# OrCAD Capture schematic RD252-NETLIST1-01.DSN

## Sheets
1 2: size A3
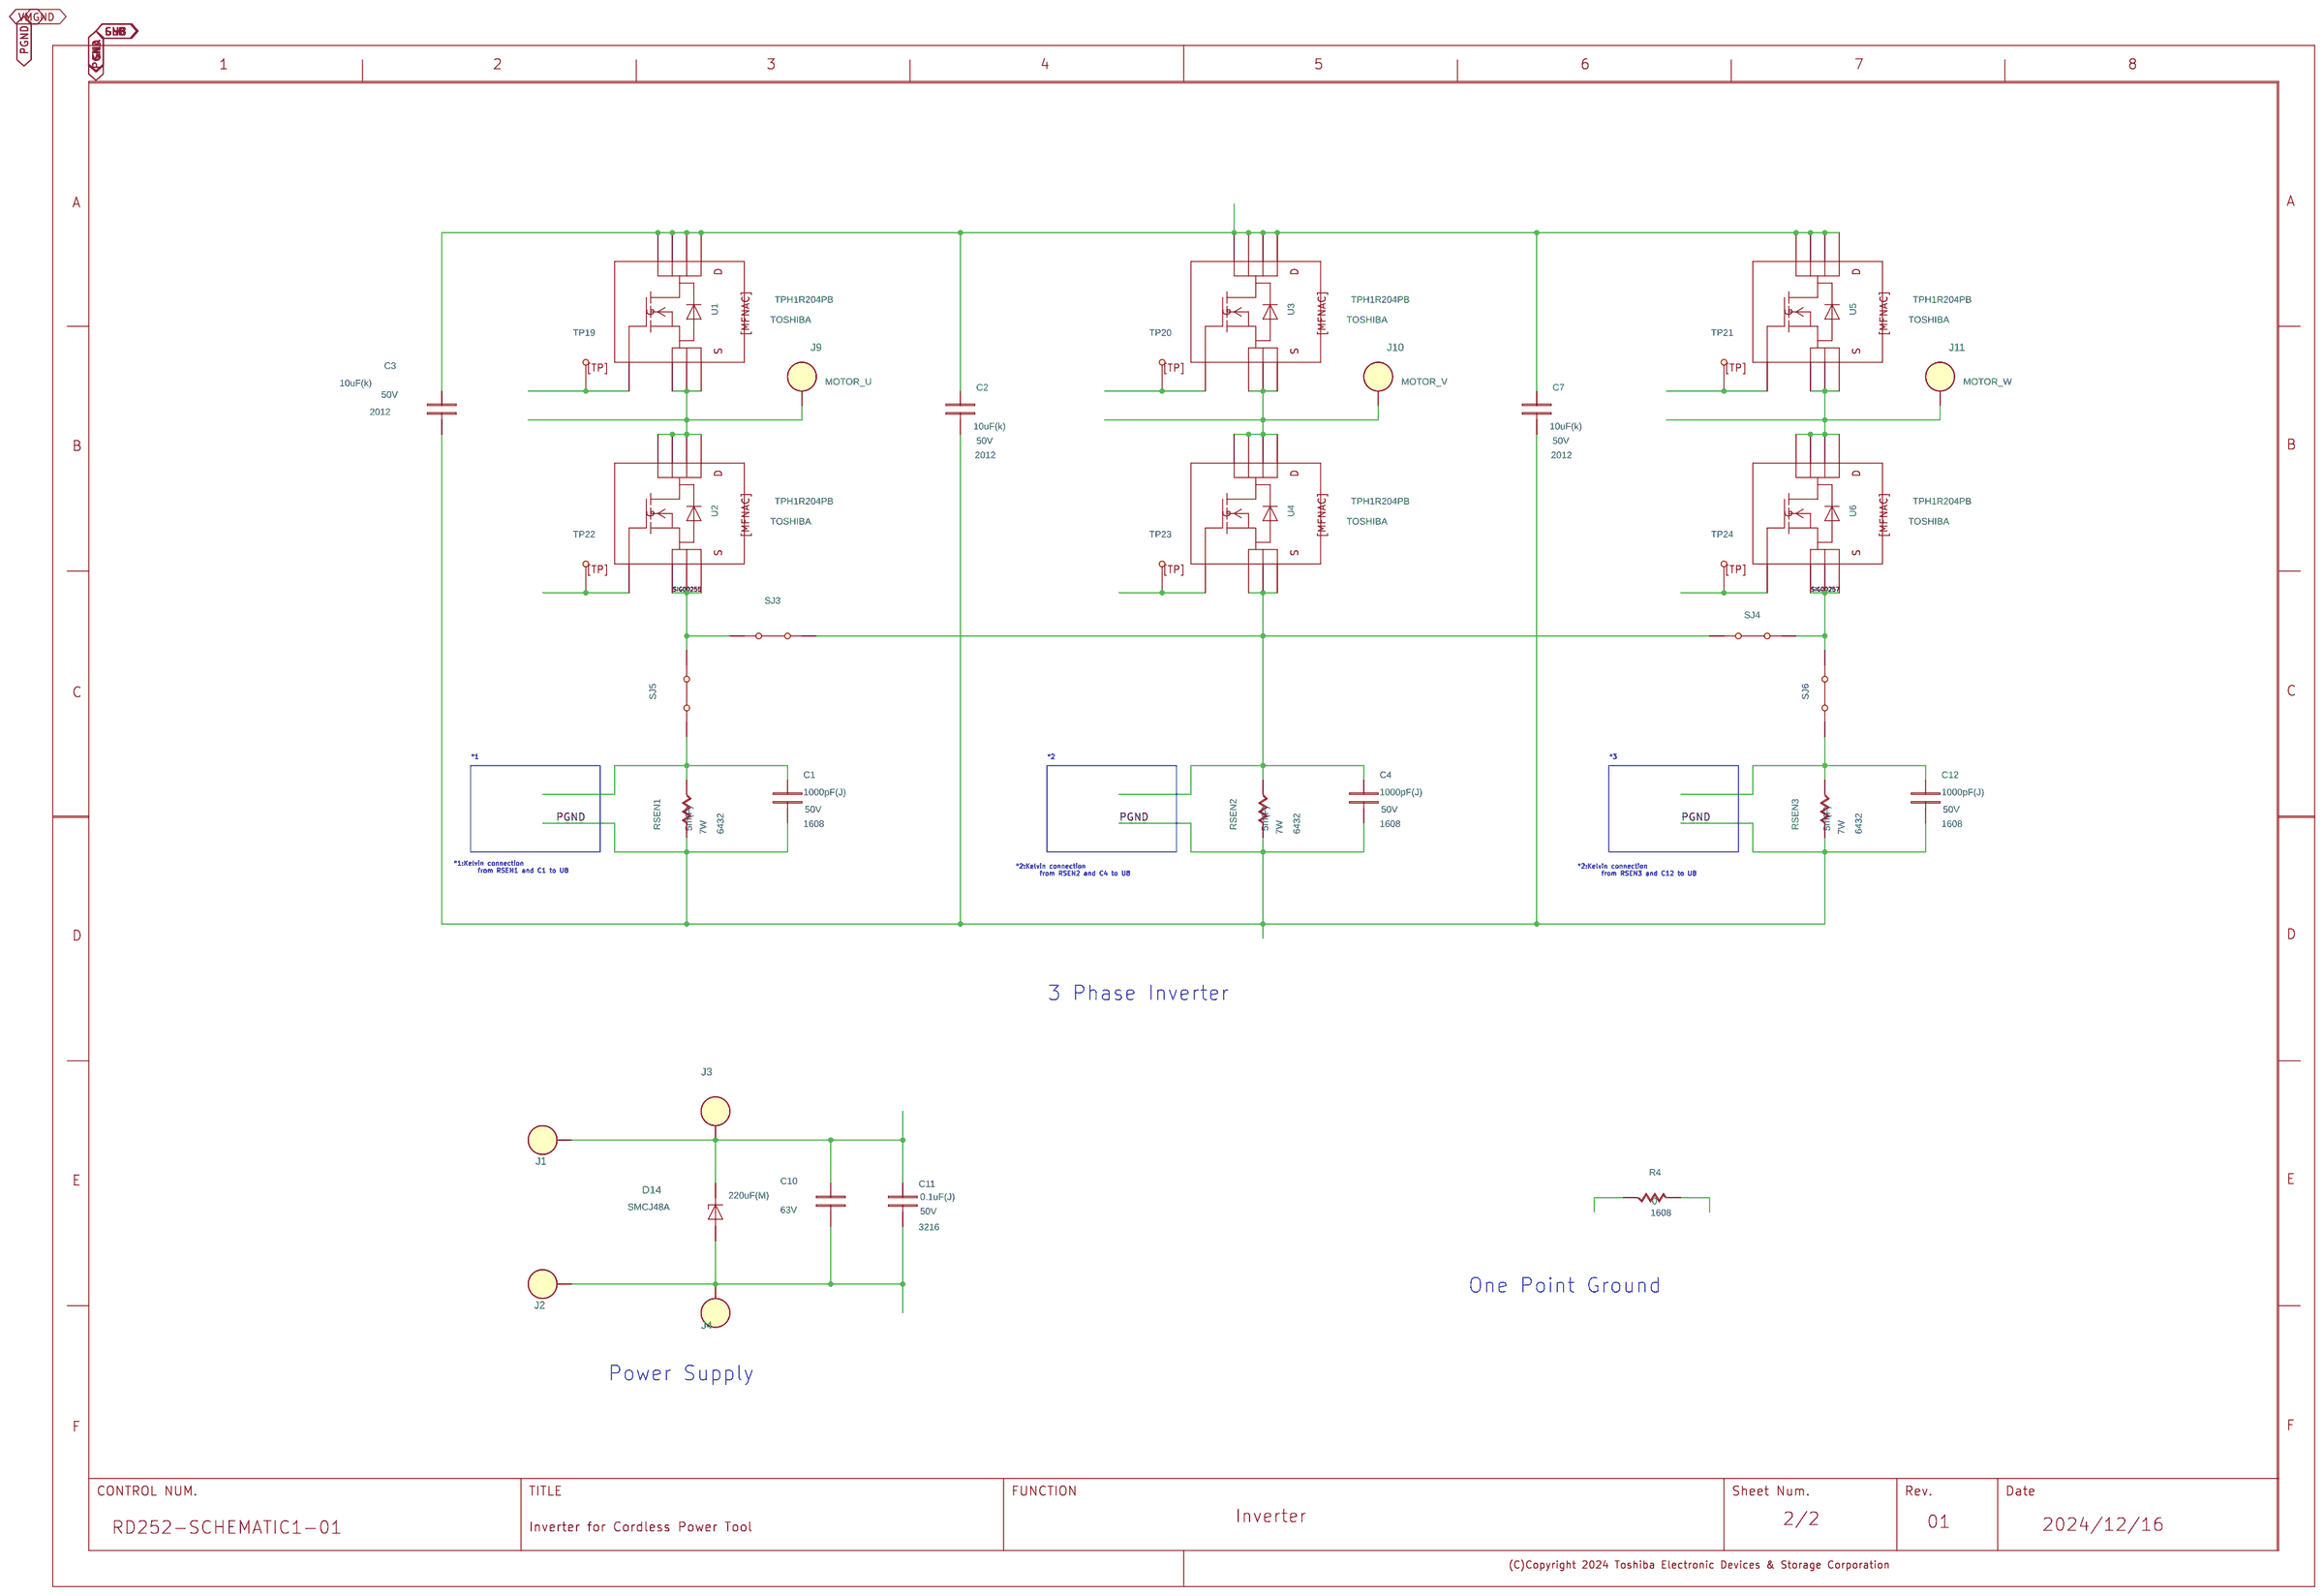
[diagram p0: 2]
2 1: size A3
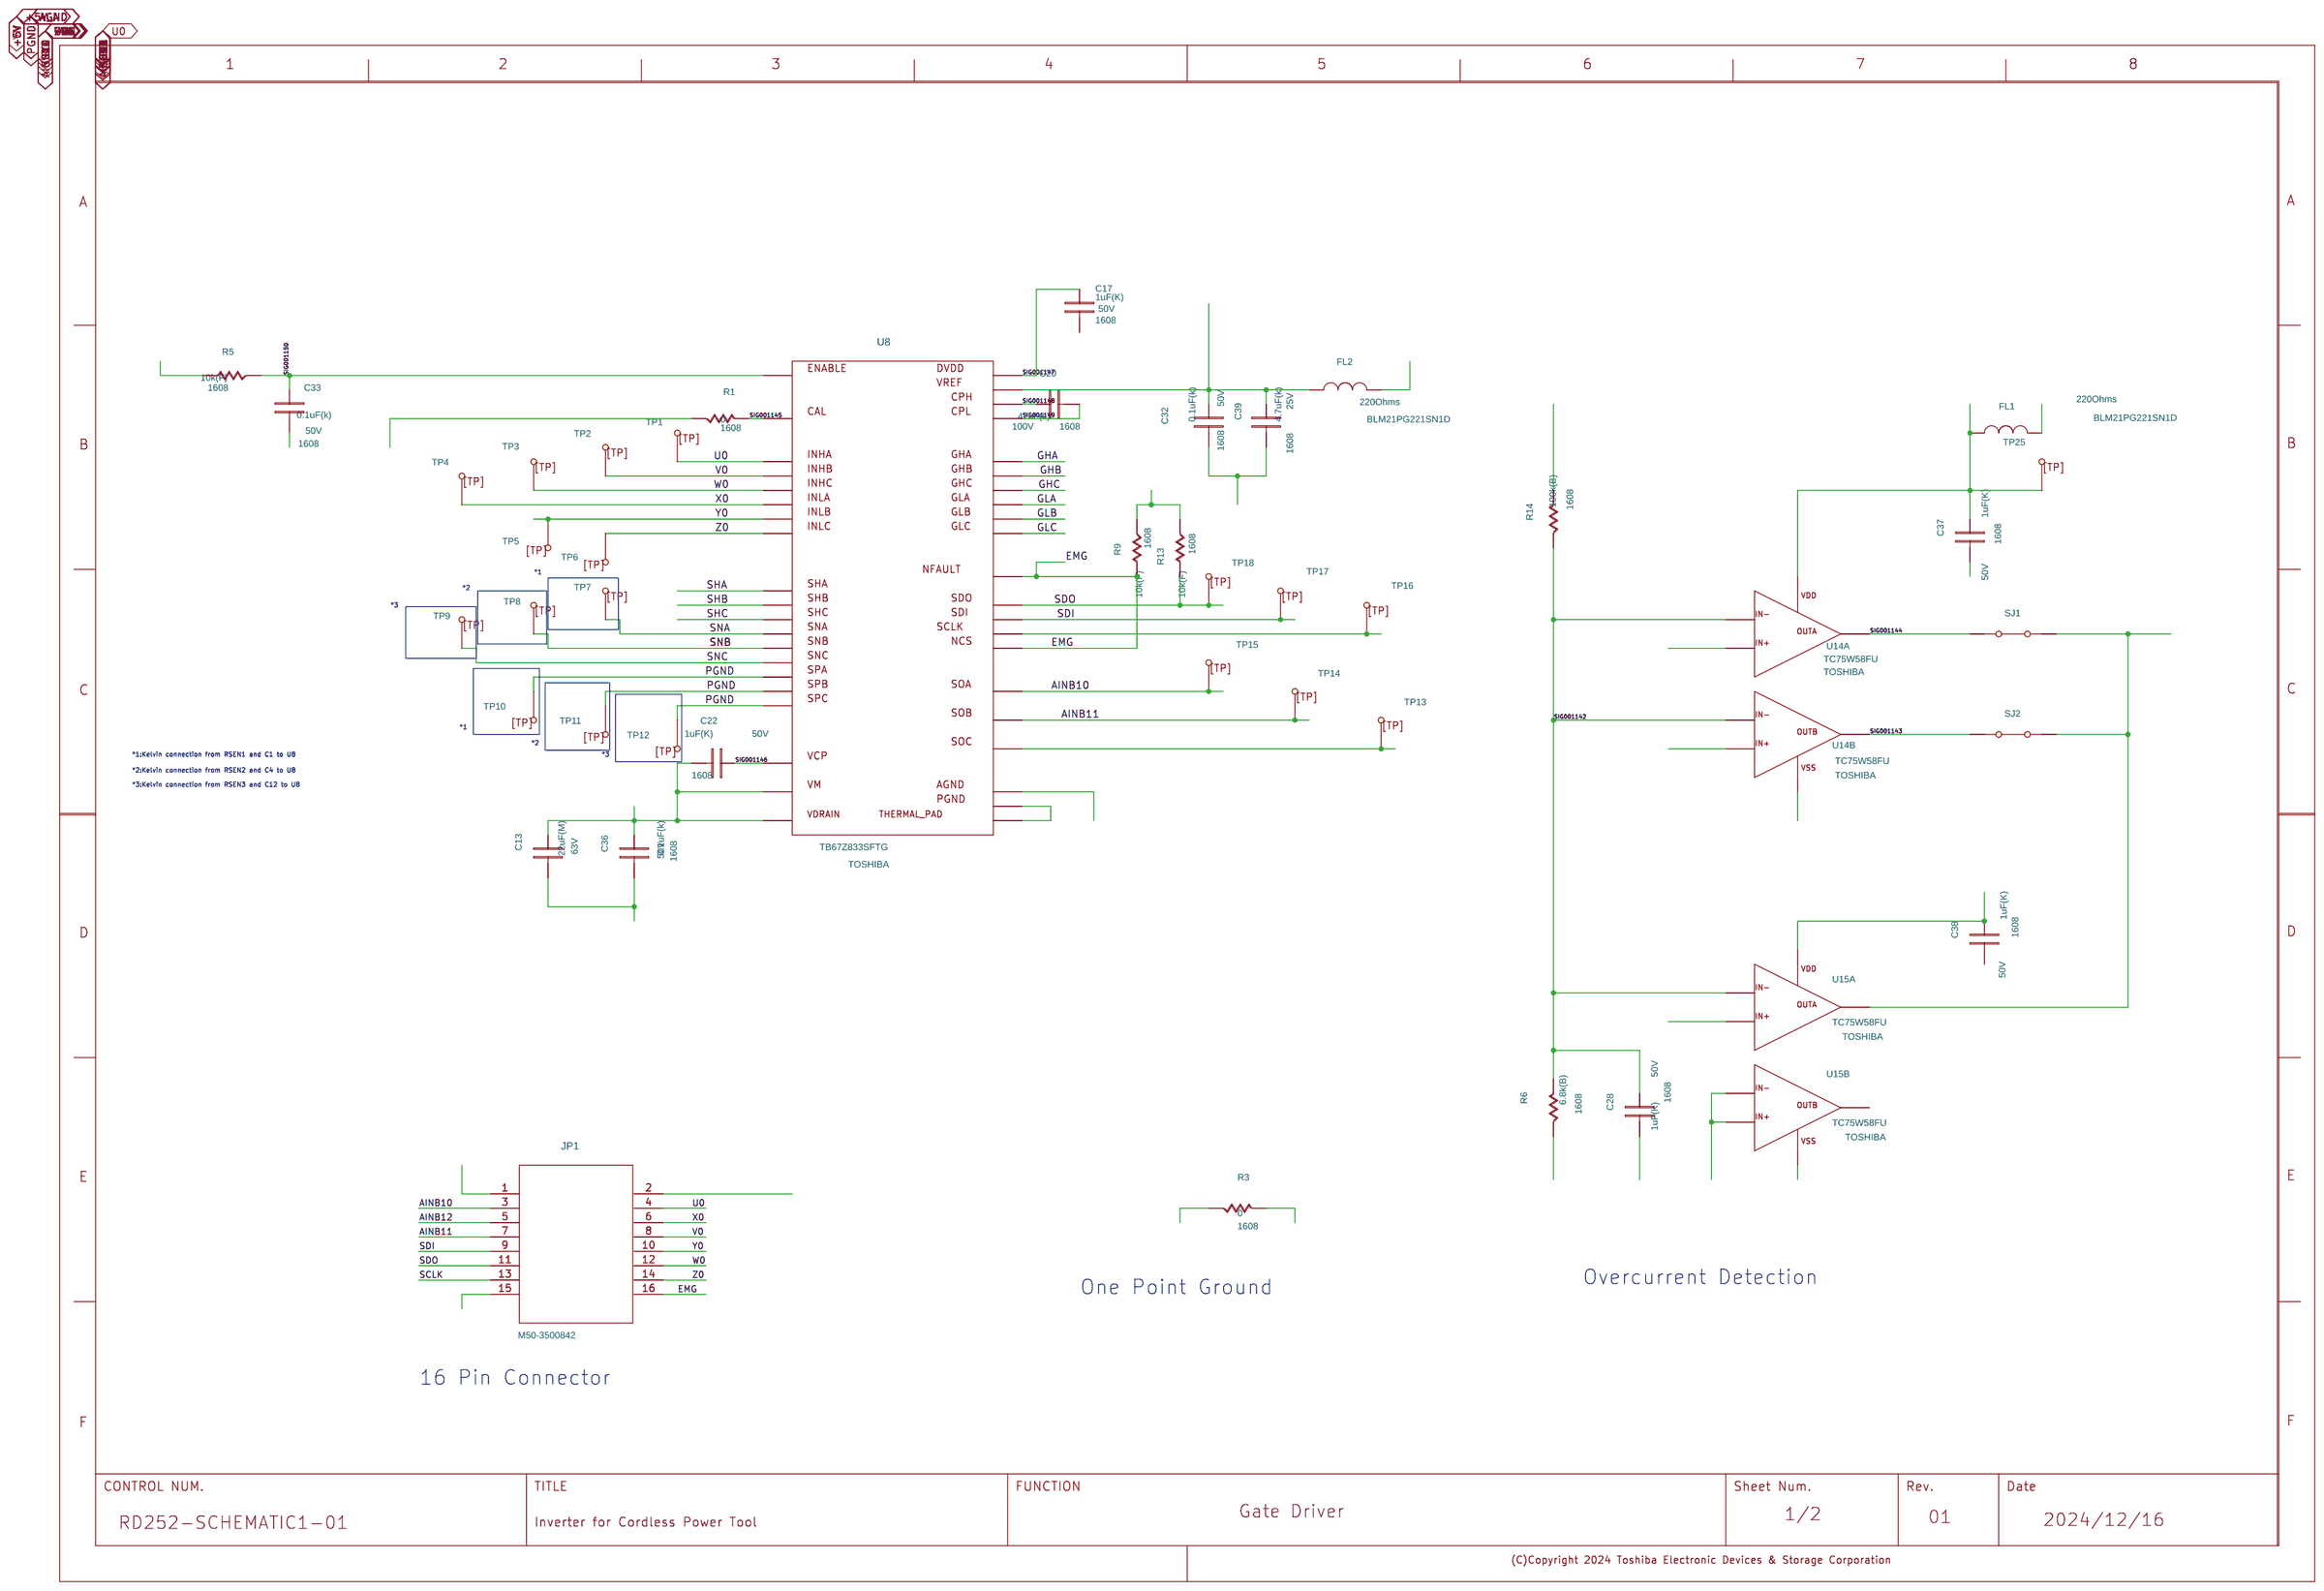
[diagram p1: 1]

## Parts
sheet 1
C13  C
C17  C
C20  C
C22  C
C28  C
C32  C
C33  C
C36  C
C37  C
C38  C
C39  C
FL1  L
FL2  L
JP1  CONN_16PINJ  [IDC16_1_27MM]
R1  R
R3  R
R5  R
R6  R
R9  R
R13  R
R14  R
SJ1  JP
SJ2  JP
TP1  TP
TP2  TP
TP3  TP
TP4  TP
TP5  TP
TP6  TP
TP7  TP
TP8  TP
TP9  TP
TP10  TP
TP11  TP
TP12  TP
TP13  TP
TP14  TP
TP15  TP
TP16  TP
TP17  TP
TP18  TP
TP25  TP
U8  DRV8323S
U14  NA  (sections A,B)
U15  NA  (sections A,B)
U?#1  WAKU_DEF100
sheet 2
C1  C
C2  C
C3  C
C4  C
C7  C
C10  C
C11  C
C12  C
D14  SMCJ22A  [DSMC]
J1  INV  [TP_SM]
J2  PGND  [TP_SM]
J3  INV  [TP_SM]
J4  PGND  [TP_SM]
J9  MOTOR_U  [TP_SM]
J10  MOTOR_U  [TP_SM]
J11  MOTOR_U  [TP_SM]
R4  R
RSEN1  R
RSEN2  R
RSEN3  R
SJ3  JP
SJ4  JP
SJ5  JP
SJ6  JP
TP19  TP
TP20  TP
TP21  TP
TP22  TP
TP23  TP
TP24  TP
U1  MFNAC
U2  MFNAC
U3  MFNAC
U4  MFNAC
U5  MFNAC
U6  MFNAC
U?#2  WAKU_DEF100

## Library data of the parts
C13 = C: COMPONENTKIND: 0; COMPONENTTYPE: 4; VAL1: 22uF(M); VAL2: 63V
C17 C37 C38 = C: COMPONENTTYPE: 4; SIZECODESMD: 1608; VAL1: 1uF(K); VAL2: 50V
C20 = C: COMPONENTKIND: 0; COMPONENTTYPE: 4; SIZECODESMD: 1608; VAL1: 47nF(k); VAL2: 100V
C22 C28 = C: COMPONENTKIND: 0; COMPONENTTYPE: 4; SIZECODESMD: 1608; VAL1: 1uF(K); VAL2: 50V
C32 C33 = C: COMPONENTTYPE: 4; SIZECODESMD: 1608; VAL1: 0.1uF(k); VAL2: 50V
C36 = C: COMPONENTKIND: 0; COMPONENTTYPE: 4; SIZECODESMD: 1608; VAL1: 0.1uF(k); VAL2: 50V
C39 = C: COMPONENTTYPE: 4; SIZECODESMD: 1608; VAL1: 4.7uF(k); VAL2: 25V
FL1 FL2 = L: COMPONENTTYPE: 4; VAL1: 220Ohms; VAL3: BLM21PG221SN1D
JP1 = CONN_16PINJ_JP1: COMPONENTKIND: 114; COMPONENTTYPE: 4; INSTANCENAME: INS1151; VAL3: M50-3500842
R1 = R: COMPONENTKIND: 0; COMPONENTTYPE: 4; SIZECODESMD: 1608; VAL1: 0; VAL2: 1A
R3 R4 = R: COMPONENTTYPE: 4; SIZECODESMD: 1608; VAL1: 0; VAL2: 1A
R5 R9 R13 = R: COMPONENTKIND: 0; COMPONENTTYPE: 4; SIZECODESMD: 1608; VAL1: 10k(F); VAL2: 330mW
R6 = R: COMPONENTTYPE: 4; SIZECODESMD: 1608; VAL1: 6.8k(B); VAL2: 200mW
R14 = R: COMPONENTTYPE: 4; SIZECODESMD: 1608; VAL1: 100k(B); VAL2: 200mW
SJ1-SJ6 = JP: COMP: SJ; COMPONENTTYPE: 4; SAVECOUNT: 0; VAL3: Solder_Jumper
TP1-TP25 = TP: COMPONENTTYPE: 4
U8 = TB67Z833SFTG_U8: COMPONENTTYPE: 4; SAVECOUNT: 3; UPDATEDATE: 2025/1/16; UPDATETIME: 19:51:29; USERCOMPTEXT3: TOSHIBA; VAL3: TB67Z833SFTG
U14 = TC75W58FU_1: COMP: TC75W58FU; COMPONENTTYPE: 8; CaptureCellPackProp: TC75W58FU_1A; SAVECOUNT: 7; UPDATEDATE: 2024/11/5; UPDATETIME: 17:40:12; USERCOMPTEXT3: TOSHIBA; VAL3: TC75W58FU
U15 = TC75W58FU_1: COMP: TC75W58FU; COMPONENTTYPE: 8; CaptureCellPackProp: TC75W58FU_1A; USERCOMPTEXT3: TOSHIBA; VAL3: TC75W58FU
U?#1 = WAKU_DEF100_1: COMPONENTTYPE: 2; DATE: 2024/12/16; DRAWINGNUMBER: RD252-SCHEMATIC1-01; FUNCTION: Gate Driver; REVISION: 01; SHEETNUMBER: 1/2; SHTSAVECOUNT: 91; TITLE: Inverter for Cordless Power Tool; UPDATEDATE: 2025.1.27; UPDATETIME: 15:35:51
C1 C4 C12 = C: COMPONENTKIND: 0; COMPONENTTYPE: 4; SIZECODESMD: 1608; VAL1: 1000pF(J); VAL2: 50V
C2 C3 C7 = C: COMPONENTTYPE: 4; SIZECODESMD: 2012; VAL1: 10uF(k); VAL2: 50V
C10 = C: COMPONENTTYPE: 4; VAL1: 220uF(M); VAL2: 63V
C11 = C: COMPONENTTYPE: 4; SIZECODESMD: 3216; VAL1: 0.1uF(J); VAL2: 50V
D14 = SMCJ22A_D14: COMP: SMCJ48A; COMPONENTKIND: 103; COMPONENTTYPE: 4; INSTANCENAME: INS1233; VAL3: SMCJ48A
J1 = 1X1HEADER_J1: COMPONENTTYPE: 4; INSTANCENAME: INS1187; SAVECOUNT: 3; UPDATEDATE: 2024/10/21; UPDATETIME: 10:49:18; UPDATEUSER: sptcae09; VAL3: Through Hole
J2 = 1X1HEADER_J2: COMPONENTTYPE: 4; INSTANCENAME: INS1195; SAVECOUNT: 3; UPDATEDATE: 2024/10/21; UPDATETIME: 10:49:19; UPDATEUSER: sptcae09; VAL3: Through Hole
J3 = 1X1HEADER_J3: COMPONENTTYPE: 4; INSTANCENAME: INS1429; SAVECOUNT: 3; UPDATEDATE: 2024/10/21; UPDATETIME: 10:49:12; UPDATEUSER: sptcae09; VAL3: Through Hole
J4 = 1X1HEADER_J4: COMPONENTTYPE: 4; INSTANCENAME: INS1437; SAVECOUNT: 3; UPDATEDATE: 2024/10/21; UPDATETIME: 10:49:13; UPDATEUSER: sptcae09; VAL3: Through Hole
J9 = 1X1HEADER_J9: COMPONENTTYPE: 4; INSTANCENAME: INS1015; SAVECOUNT: 3; UPDATEDATE: 2024/10/21; UPDATETIME: 10:49:12; UPDATEUSER: sptcae09; USEWITHLAYOUT: YES
J10 = 1X1HEADER_J9: COMPONENTTYPE: 4; INSTANCENAME: INS1015; SAVECOUNT: 3; UPDATEDATE: 2024/10/21; UPDATETIME: 10:49:12; UPDATEUSER: sptcae09; USEWITHLAYOUT: YES; VAL3: MOTOR_V
J11 = 1X1HEADER_J9: COMPONENTTYPE: 4; INSTANCENAME: INS1015; SAVECOUNT: 3; UPDATEDATE: 2024/10/21; UPDATETIME: 10:49:12; UPDATEUSER: sptcae09; USEWITHLAYOUT: YES; VAL3: MOTOR_W
RSEN1-RSEN3 = R: COMPONENTTYPE: 4; SIZECODESMD: 6432; VAL1: 5m(F); VAL2: 7W
U1-U6 = MFNAC: COMP: TPH1R204PB; COMPONENTTYPE: 4; USERCOMPTEXT3: TOSHIBA; VAL3: TPH1R204PB
U?#2 = WAKU_DEF100_1: COMPONENTTYPE: 2; DATE: 2024/12/16; DRAWINGNUMBER: RD252-SCHEMATIC1-01; FUNCTION: Inverter; REVISION: 01; SHEETNUMBER: 2/2; SHTSAVECOUNT: 40; TITLE: Inverter for Cordless Power Tool; UPDATEDATE: 2024.12.16; UPDATETIME: 10:34:52; UPDATEUSER: sptcae09

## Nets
+5V: C17.2 C28.2 C32.2 C37.2 C38.2 C39.2 JP1.15 R3.1 R6.2 U8.32 U14.4 U15.4 U15.5 U15.6
+5V (page 1): FL1.1 FL2.2 JP1.1 R5.1 R9.2 R13.2
+5V_A: C32.1 C37.1 C38.1 C39.1 FL1.2 FL2.1 R14.1 TP25.1 U8.24 U14.8 U15.8
GND: C33.2 JP1.2 R1.2 R3.2 R4.1
PGND: C1.2 C2.2 C3.2 C4.2 C7.2 C10.2 C11.2 C12.2 C13.2 C36.2 D14.A J2.1 J4.1 R4.2 RSEN1.1 RSEN2.1 RSEN3.1 TP10.1 TP11.1 TP12.1 U8.9 U8.12 U8.19 U8.40 U8.41
V0: JP1.8 TP2.1 U8.36
AINB10: JP1.3 TP15.1 U8.23 U14.3
AINB11: JP1.7 TP14.1 U8.22 U15.3
AINB12: JP1.5 TP13.1 U8.21 U14.5
EMG: JP1.16 R9.1 SJ1.2 SJ2.2 U8.25 U8.29 U15.1
GHA: TP19.1 U1.4 U8.6
GHB: TP20.1 U3.4 U8.15
GHC: TP21.1 U5.4 U8.16
GLA: TP22.1 U2.4 U8.8
GLB: TP23.1 U4.4 U8.13
GLC: TP24.1 U6.4 U8.18
SCLK: JP1.13 TP16.1 U8.28
SDI: JP1.9 TP17.1 U8.27
SDO: JP1.11 R13.1 TP18.1 U8.26
SHA: J9.1 U1.1 U1.2 U1.3 U2.5 U2.6 U2.7 U2.8 U8.7
SHB: J10.1 U3.1 U3.2 U3.3 U4.5 U4.6 U4.7 U4.8 U8.14
SHC: J11.1 U5.1 U5.2 U5.3 U6.5 U6.6 U6.7 U6.8 U8.17
SIG00255: SJ3.1 SJ5.2 U2.1 U2.2 U2.3
SIG00257: SJ4.2 SJ6.2 U6.1 U6.2 U6.3
SIG001142: C28.1 R6.1 R14.2 U14.2 U14.6 U15.2
SIG001143: SJ2.1 U14.7
SIG001144: SJ1.1 U14.1
SIG001145: R1.1 U8.31
SIG001146: C22.1 U8.3
SIG001147: C17.1 U8.33
SIG001148: C20.1 U8.2
SIG001149: C20.2 U8.1
SIG001150: C33.1 R5.2 U8.30
SNA: C1.1 RSEN1.2 SJ5.1 TP7.1 U8.10
SNB: C4.1 RSEN2.2 SJ3.2 SJ4.1 TP8.1 U4.1 U4.2 U4.3 U8.11
SNC: C12.1 RSEN3.2 SJ6.1 TP9.1 U8.20
U0: JP1.4 TP1.1 U8.34
VM: C13.1 C22.2 C36.1 U8.4 U8.5
VM (page 2): C2.1 C3.1 C7.1 C10.1 C11.1 D14.C J1.1 J3.1 U1.5 U1.6 U1.7 U1.8 U3.5 U3.6 U3.7 U3.8 U5.5 U5.6 U5.7 U5.8
W0: JP1.12 TP3.1 U8.38
X0: JP1.6 TP4.1 U8.35
Y0: JP1.10 TP5.1 U8.37
Z0: JP1.14 TP6.1 U8.39

Not connected (* = marked no-connect by the designer): U15 7

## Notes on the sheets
sheet 1
- *1
- *2
- *3
- *1:Kelvin connection
         from RSEN1 and C1 to U8
- *2:Kelvin connection
         from RSEN2 and C4 to U8
- *2:Kelvin connection
         from RSEN3 and C12 to U8
- 3 Phase Inverter
- One Point Ground
- Power Supply
sheet 2
- *1
- *2
- *3
- *1
- *1:Kelvin connection from RSEN1 and C1 to U8
- *2
- *3
- *2:Kelvin connection from RSEN2 and C4 to U8
- *3:Kelvin connection from RSEN3 and C12 to U8
- One Point Ground
- Overcurrent Detection
- 16 Pin Connector
